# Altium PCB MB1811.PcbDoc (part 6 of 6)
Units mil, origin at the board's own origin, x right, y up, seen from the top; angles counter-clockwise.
Board outline 3480.3 x 4291.34 mil, 4 copper layers (Top Layer, L2_VCC, L3_GND, Bottom Layer), stack 30.59 mil thick; 371 components, 285 nets, 1369 pads, 606 vias.
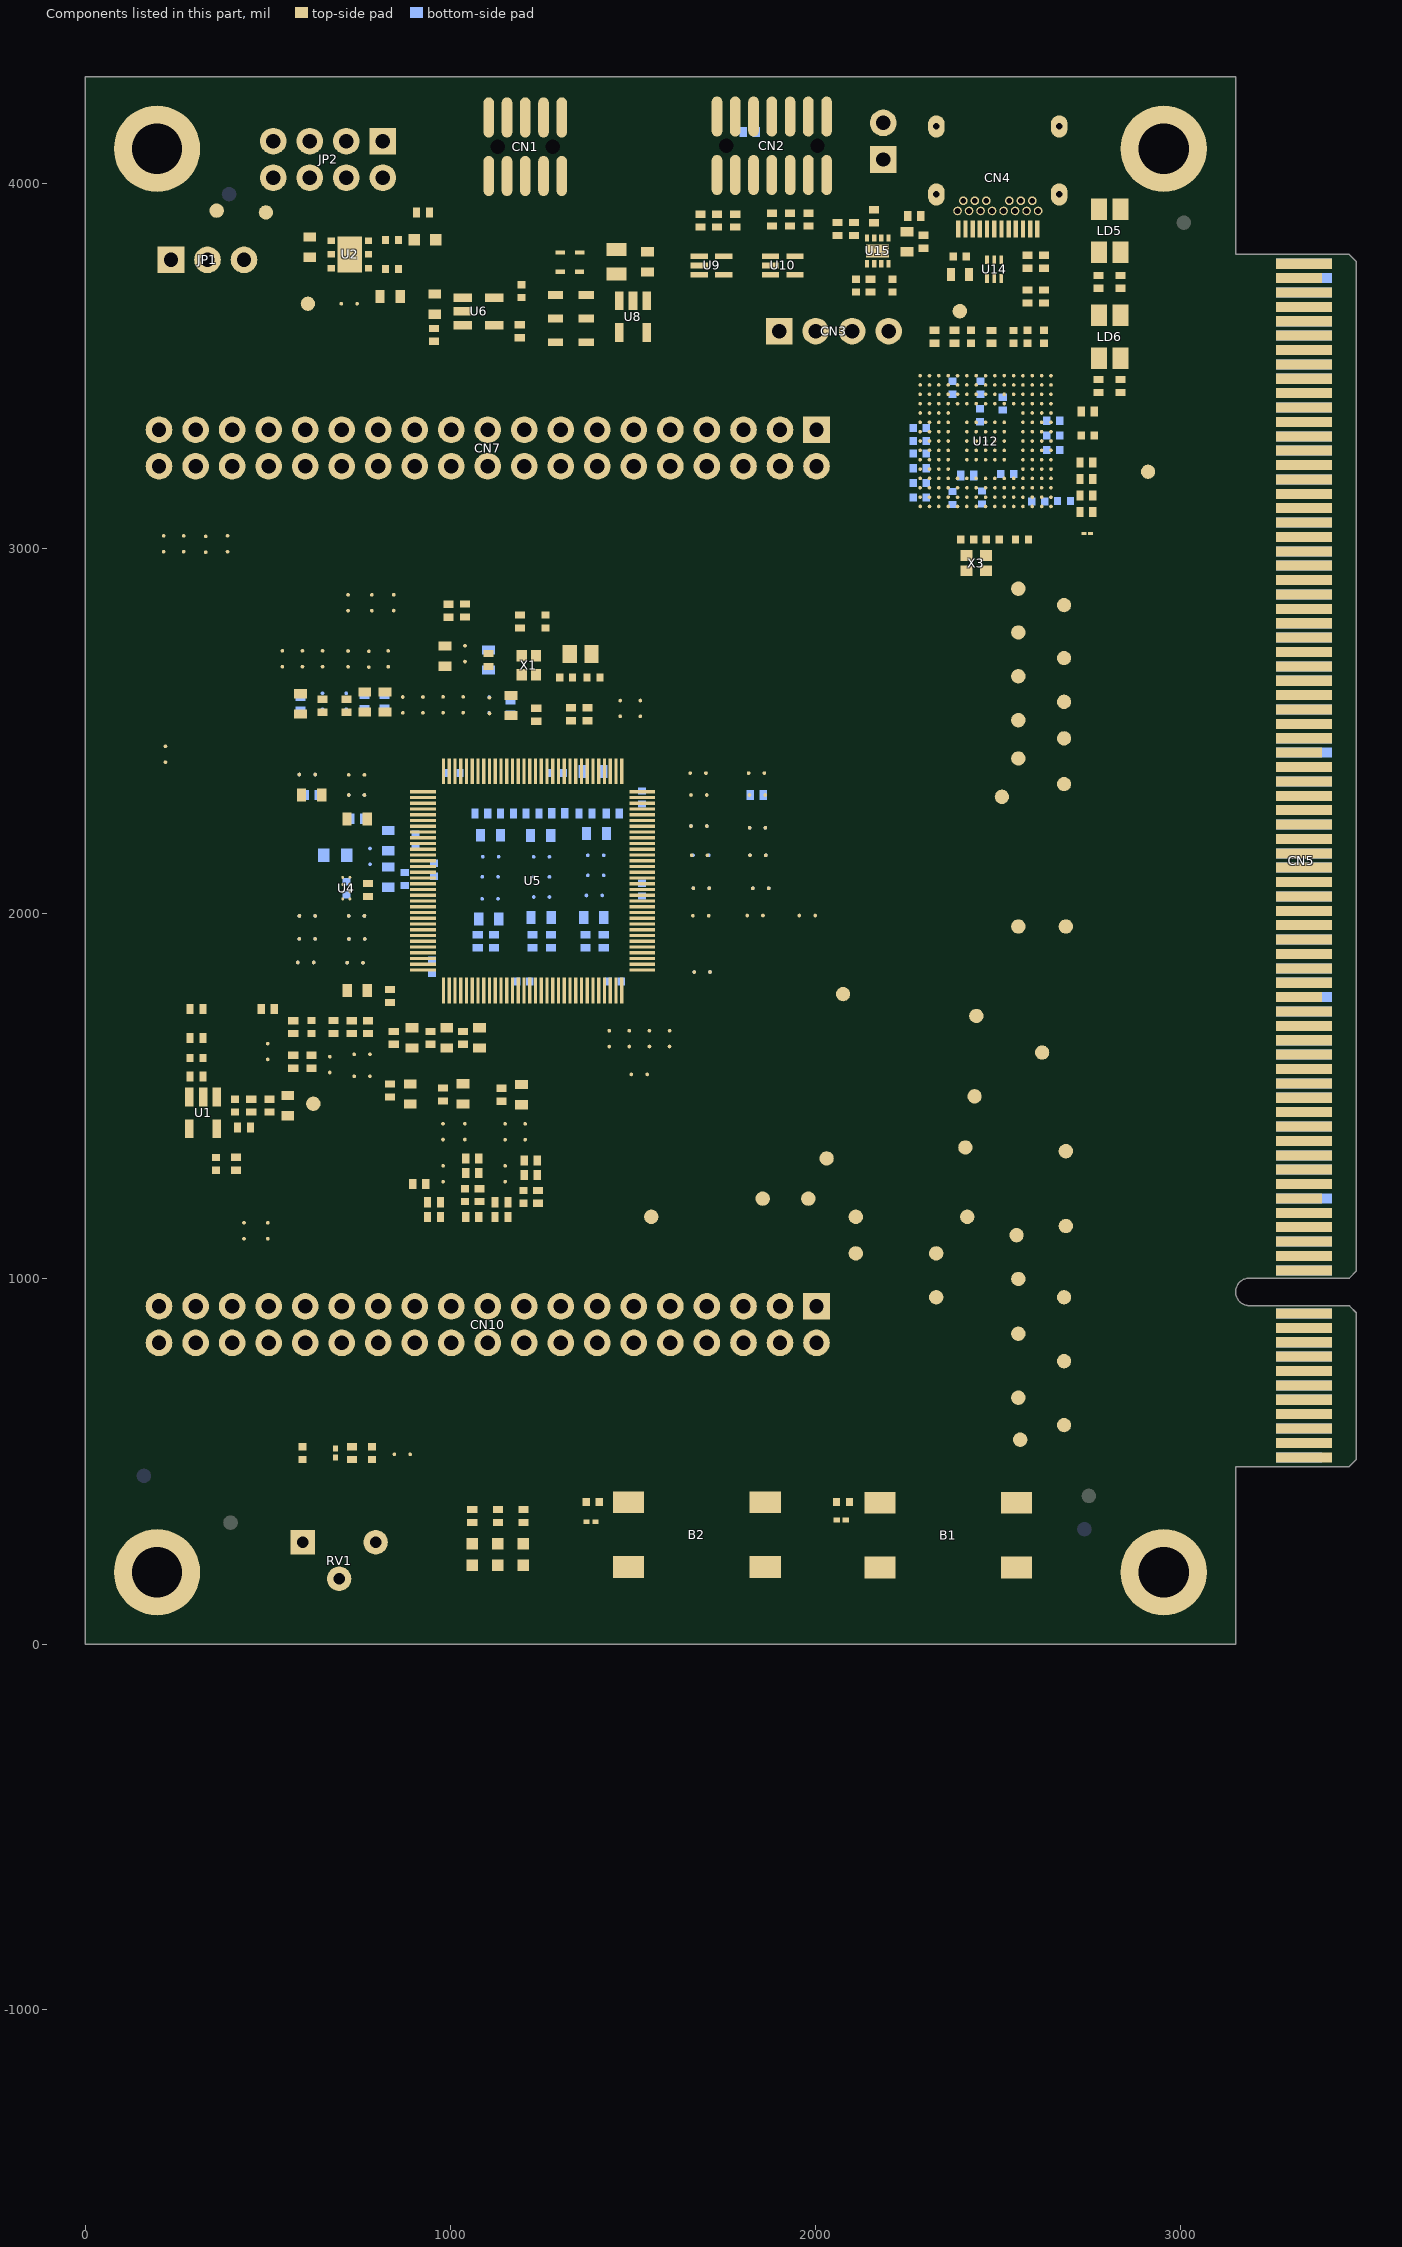
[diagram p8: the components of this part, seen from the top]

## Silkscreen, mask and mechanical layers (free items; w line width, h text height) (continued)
M21-Bottom Title Box:
  circle w10: c8,-1484.81 r51.18
  region: 26.69,-1199.92 638,-1199.92 665.33,-1269.81 713,-1318.04 768,-1244.81 768,-1179.81 723,-1124.81 666.46,-1109.92 26.69,-1109.92
  region: 578,-1527.85 1001.46,-1527.85 962.35,-1429.71 653,-1429.71 635.33,-1399.81 548.38,-1500.14
  lines w10: 6.46,-1109.92 36.46,-1199.92 ; 16.46,-1109.92 46.46,-1199.92 ; 23,-1109.81 53,-1199.81 ; 26.46,-1199.92 -3.54,-1109.92 656.46,-1109.92 cw(c665.92,-1213.89) 736.93,-1290.42 616.22,-1429.71 962.35,-1429.71 ; 26.69,-1199.92 172.06,-1199.92 ; 130.54,-1460.25 -38.72,-1035.94 727.01,-1035.94 ; 130.58,-1460.34 ccw(c230.94,-1420.2) 240.73,-1527.85 1001.46,-1527.85 830.35,-1098.91 ; 172.06,-1189.92 285.81,-1519.81 ; 181.06,-1190.26 294.03,-1517.85 ; 191.06,-1190.26 304.03,-1517.85 ; 201.06,-1190.26 314.03,-1517.85 ; 211.06,-1190.26 324.03,-1517.85 ; 221.06,-1190.26 334.03,-1517.85 ; 231.06,-1190.26 344.03,-1517.85 ; 236.46,-1199.92 748,-1199.92 ; 241.06,-1190.26 354.03,-1517.85 ; 251.06,-1190.26 364.03,-1517.85 ; 256.06,-1190.26 369.03,-1517.85 ; 264.03,-1189.92 377.78,-1519.81 ; 513,-1434.81 721.86,-1193.82 ; 513,-1419.81 721.86,-1178.82 ; 518,-1449.81 726.86,-1208.82 ; 518,-1439.81 726.86,-1198.82 ; 518,-1404.81 726.86,-1163.82 ; 520.14,-1457.34 726.86,-1218.82 ; 520.84,-1387.94 729.7,-1146.95 ; 523,-1464.81 731.86,-1223.82 ; 528,-1469.81 736.86,-1228.82 ; 533,-1474.81 741.86,-1233.82 ; 538,-1479.81 746.86,-1238.82 ; 543,-1494.81 751.86,-1253.82 ; 543,-1484.81 751.86,-1243.82 ; 548.38,-1500.14 761.86,-1253.82 ; 588.17,-1524.22 cw(c617.01,-1423.88) 546,-1347.35 639.1,-1239.92 ccw(c626.1,-1221.73) 625.08,-1199.39 ; 652,-1391.17 ccw(c663.72,-1409.16) 667.85,-1430.23 ; 727.06,-1035.94 cw(c736.38,-1138.39) 831.89,-1100.18
  lines w11.81: 285.81,-1519.81 377.78,-1519.81 ; 1063.79,-1680.85 1063.79,-893.45 ; 1063.79,-1484 3426,-1484 ; 1063.79,-1287.15 3426,-1287.15 ; 1063.79,-1090.3 3426,-1090.3 ; 1851.19,-1680.85 1851.19,-1090.3 ; -117.31,-1680.85 -117.31,-893.45 3426,-893.45 3426,-1680.85 -117.31,-1680.85
  text "Project: '.Board_Name'" at 3378.99,-1020.06 h118.11
  text "Gerber:" at 1804.63,-1220.22 h118.11
  text "Layer:" at 3378.98,-1220.22 h118.11
  text "Ref: '.Board_Reference'" at 1804.63,-1417.07 h118.11
  text "Variant: '.VariantName'" at 3378.99,-1417.07 h118.11
  text "R" at 28,-1514.81 h60
  text "Rev: '.Board_PCB_Revision'" at 1806.87,-1613.92 h118.11
  text "Date: '.Board_Document_Date'" at 3378.99,-1613.92 h118.11

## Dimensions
-0.01,4291.35 to 3149.58,4291.35 on Drill Drawing
-0.01,4291.35 to -0.01,0.01 on Drill Drawing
